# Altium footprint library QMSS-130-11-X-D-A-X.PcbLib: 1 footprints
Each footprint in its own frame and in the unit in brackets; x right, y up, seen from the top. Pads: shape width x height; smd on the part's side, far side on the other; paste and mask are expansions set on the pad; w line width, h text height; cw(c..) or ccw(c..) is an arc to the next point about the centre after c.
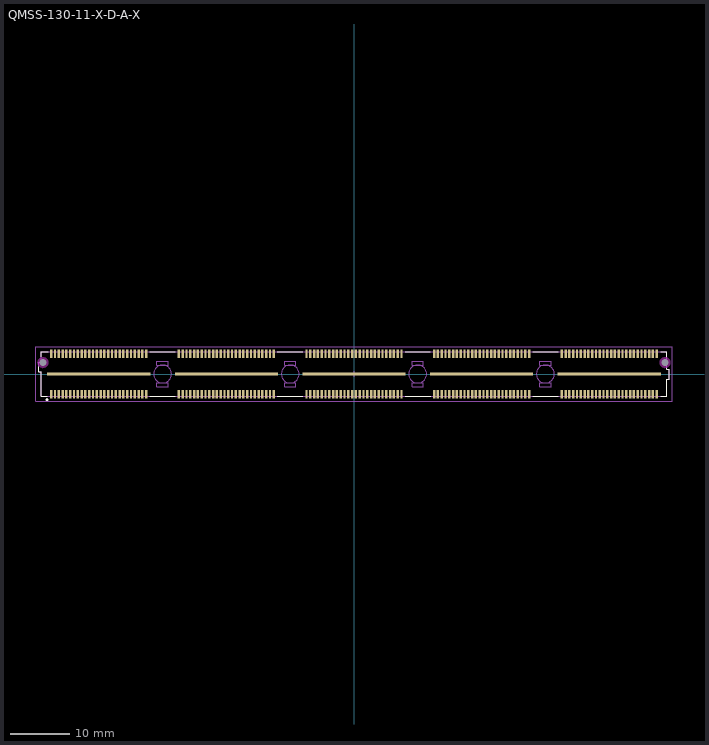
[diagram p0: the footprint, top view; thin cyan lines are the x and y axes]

## QMSS-130-11-X-D-A-X [mm] "0.635mm pitch, 260 pin, high speed shielded terminal; w/5 banks, w/40 signal pin/bank, w/12 GND pin/bank"
height 6.35
pads (267):
  rect 0.4x1.4 smd mask+0: 1(-50.62,-3.365) 2(-50.62,3.365) 3(-49.985,-3.365) 4(-49.985,3.365) 5(-49.35,-3.365) 6(-49.35,3.365) 7(-48.715,-3.365) 8(-48.715,3.365) 9(-48.08,-3.365) 10(-48.08,3.365) 11(-47.445,-3.365) 12(-47.445,3.365) 13(-46.81,-3.365) 14(-46.81,3.365) 15(-46.175,-3.365) 16(-46.175,3.365) 17(-45.54,-3.365) 18(-45.54,3.365) 19(-44.905,-3.365) 20(-44.905,3.365) 21(-44.27,-3.365) 22(-44.27,3.365) 23(-43.635,-3.365) 24(-43.635,3.365) 25(-43,-3.365) 26(-43,3.365) 27(-42.365,-3.365) 28(-42.365,3.365) 29(-41.73,-3.365) 30(-41.73,3.365) 31(-41.095,-3.365) 32(-41.095,3.365) 33(-40.46,-3.365) 34(-40.46,3.365) 35(-39.825,-3.365) 36(-39.825,3.365) 37(-39.19,-3.365) 38(-39.19,3.365) 39(-38.555,-3.365) 40(-38.555,3.365) 41(-37.92,-3.365) 42(-37.92,3.365) 43(-37.285,-3.365) 44(-37.285,3.365) 45(-36.65,-3.365) 46(-36.65,3.365) 47(-36.015,-3.365) 48(-36.015,3.365) 49(-35.38,-3.365) 50(-35.38,3.365) 51(-34.745,-3.365) 52(-34.745,3.365) 53(-13.405,3.365) 54(-13.405,-3.365) 55(-14.04,3.365) 56(-14.04,-3.365) 57(-14.675,-3.365) 58(-14.675,3.365) 59(-15.31,3.365) 60(-15.31,-3.365) 61(-15.945,3.365) 62(-15.945,-3.365) 63(-16.58,3.365) 64(-16.58,-3.365) 65(-17.215,-3.365) 66(-17.215,3.365) 67(-17.85,3.365) 68(-17.85,-3.365) 69(-18.485,3.365) 70(-18.485,-3.365) 71(-19.12,3.365) 72(-19.12,-3.365) 73(-19.755,-3.365) 74(-19.755,3.365) 75(-20.39,3.365) 76(-20.39,-3.365) 77(-21.025,3.365) 78(-21.025,-3.365) 79(-21.66,3.365) 80(-21.66,-3.365) 81(-22.295,3.365) 82(-22.295,-3.365) 83(-22.93,-3.365) 84(-22.93,3.365) 85(-23.565,-3.365) 86(-23.565,3.365) 87(-24.2,3.365) 88(-24.2,-3.365) 89(-24.835,-3.365) 90(-24.835,3.365) 91(-25.47,-3.365) 92(-25.47,3.365) 93(-26.105,3.365) 94(-26.105,-3.365) 95(-26.74,-3.365) 96(-26.74,3.365) 97(-27.375,-3.365) 98(-27.375,3.365) 99(-28.01,3.365) 100(-28.01,-3.365) 101(-28.645,-3.365) 102(-28.645,3.365) 103(-29.28,3.365) 104(-29.28,-3.365) 105(7.935,3.365) 106(7.935,-3.365) 107(7.3,3.365) 108(7.3,-3.365) 109(6.665,-3.365) 110(6.665,3.365) 111(6.03,3.365) 112(6.03,-3.365) 113(5.395,3.365) 114(5.395,-3.365) 115(4.76,3.365) 116(4.76,-3.365) 117(4.125,-3.365) 118(4.125,3.365) 119(3.49,3.365) 120(3.49,-3.365) 121(2.855,3.365) 122(2.855,-3.365) 123(2.22,3.365) 124(2.22,-3.365) 125(1.585,-3.365) 126(1.585,3.365) 127(0.95,3.365) 128(0.95,-3.365) 129(0.315,3.365) 130(0.315,-3.365) 131(-0.32,3.365) 132(-0.32,-3.365) 133(-0.955,3.365) 134(-0.955,-3.365) 135(-1.59,-3.365) 136(-1.59,3.365) 137(-2.225,-3.365) 138(-2.225,3.365) 139(-2.86,3.365) 140(-2.86,-3.365) 141(-3.495,-3.365) 142(-3.495,3.365) 143(-4.13,-3.365) 144(-4.13,3.365) 145(-4.765,3.365) 146(-4.765,-3.365) 147(-5.4,-3.365) 148(-5.4,3.365) 149(-6.035,-3.365) 150(-6.035,3.365) 151(-6.67,3.365) 152(-6.67,-3.365) 153(-7.305,-3.365) 154(-7.305,3.365) 155(-7.94,3.365) 156(-7.94,-3.365) 157(29.275,3.365) 158(29.275,-3.365) 159(28.64,3.365) 160(28.64,-3.365) 161(28.005,-3.365) 162(28.005,3.365) 163(27.37,3.365) 164(27.37,-3.365) 165(26.735,3.365) 166(26.735,-3.365) 167(26.1,3.365) 168(26.1,-3.365) 169(25.465,-3.365) 170(25.465,3.365) 171(24.83,3.365) 172(24.83,-3.365) 173(24.195,3.365) 174(24.195,-3.365) 175(23.56,3.365) 176(23.56,-3.365) 177(22.925,-3.365) 178(22.925,3.365) 179(22.29,3.365) 180(22.29,-3.365) 181(21.655,3.365) 182(21.655,-3.365) 183(21.02,3.365) 184(21.02,-3.365) 185(20.385,3.365) 186(20.385,-3.365) 187(19.75,-3.365) 188(19.75,3.365) 189(19.115,-3.365) 190(19.115,3.365) 191(18.48,3.365) 192(18.48,-3.365) 193(17.845,-3.365) 194(17.845,3.365) 195(17.21,-3.365) 196(17.21,3.365) 197(16.575,3.365) 198(16.575,-3.365) 199(15.94,-3.365) 200(15.94,3.365) 201(15.305,-3.365) 202(15.305,3.365) 203(14.67,3.365) 204(14.67,-3.365) 205(14.035,-3.365) 206(14.035,3.365) 207(13.4,3.365) 208(13.4,-3.365) 209(50.615,3.365) 210(50.615,-3.365) 211(49.98,3.365) 212(49.98,-3.365) 213(49.345,-3.365) 214(49.345,3.365) 215(48.71,3.365) 216(48.71,-3.365) 217(48.075,3.365) 218(48.075,-3.365) 219(47.44,3.365) 220(47.44,-3.365) 221(46.805,-3.365) 222(46.805,3.365) 223(46.17,3.365) 224(46.17,-3.365) 225(45.535,3.365) 226(45.535,-3.365) 227(44.9,3.365) 228(44.9,-3.365) 229(44.265,-3.365) 230(44.265,3.365) 231(43.63,3.365) 232(43.63,-3.365) 233(42.995,3.365) 234(42.995,-3.365) 235(42.36,3.365) 236(42.36,-3.365) 237(41.725,3.365) 238(41.725,-3.365) 239(41.09,-3.365) 240(41.09,3.365) 241(40.455,-3.365) 242(40.455,3.365) 243(39.82,3.365) 244(39.82,-3.365) 245(39.185,-3.365) 246(39.185,3.365) 247(38.55,-3.365) 248(38.55,3.365) 249(37.915,3.365) 250(37.915,-3.365) 251(37.28,-3.365) 252(37.28,3.365) 253(36.645,-3.365) 254(36.645,3.365) 255(36.01,3.365) 256(36.01,-3.365) 257(35.375,-3.365) 258(35.375,3.365) 259(34.74,3.365) 260(34.74,-3.365)
  rect 17.25x0.5 smd mask+0: 261(-42.68,0) 262(-21.34,0) 263(0,0) 264(21.34,0) 265(42.68,0)
  round 1 hole 1.2 unplated mask+0: 266(-52.015,1.91) 267(51.995,1.91)
Top Overlay:
  circle w0.25: c-51.35,-4.3 r0.125
  lines w0.2: -52.7,1.2 -52.7,0.35 -52.3,0.35 -52.3,-3.75 -51.25,-3.75 ; -52.3,2.85 -52.3,3.75 -51.15,3.75 ; -34.15,-3.75 -29.9,-3.75 ; -34.15,3.75 -29.9,3.75 ; -12.8,-3.75 -8.55,-3.75 ; -12.8,3.75 -8.55,3.75 ; 8.55,-3.75 12.8,-3.75 ; 8.55,3.75 12.75,3.75 ; 29.85,-3.75 34.15,-3.75 ; 29.85,3.75 34.15,3.75 ; 51.25,-3.75 52.3,-3.75 52.3,-0.85 52.7,-0.85 52.7,0.8 52.3,0.8 52.3,0.95 ; 51.25,3.75 52.3,3.75 52.3,2.85
Keep-Out Layer:
  pour cut-out: 52.903,1.91 52.872,2.145 52.781,2.364 52.637,2.552 52.449,2.696 52.23,2.787 51.995,2.818 51.76,2.787 51.541,2.696 51.353,2.552 51.209,2.364 51.118,2.145 51.087,1.91 51.118,1.675 51.209,1.456 51.353,1.268 51.541,1.124 51.76,1.033 51.995,1.002 52.23,1.033 52.449,1.124 52.637,1.268 52.781,1.456 52.872,1.675
  pour cut-out: -51.107,1.91 -51.138,2.145 -51.229,2.364 -51.373,2.552 -51.561,2.696 -51.78,2.787 -52.015,2.818 -52.25,2.787 -52.469,2.696 -52.657,2.552 -52.801,2.364 -52.892,2.145 -52.923,1.91 -52.892,1.675 -52.801,1.456 -52.657,1.268 -52.469,1.124 -52.25,1.033 -52.015,1.002 -51.78,1.033 -51.561,1.124 -51.373,1.268 -51.229,1.456 -51.138,1.675
Mechanical 12:
  lines w0.001: -52.7,0.35 -52.7,2 -52.3,2 -52.3,3.75 52.3,3.75 52.3,0.8 52.7,0.8 52.7,-0.85 52.3,-0.85 52.3,-3.75 -52.3,-3.75 -52.3,0.35 -52.7,0.35
Mechanical 13:
  circle w0.1: c-32,0 r1.5
  circle w0.1: c-10.65,0 r1.5
  circle w0.1: c10.65,0 r1.5
  circle w0.1: c32,0 r1.5
  lines w0.1: -52.7,0.35 -52.7,2 -52.3,2 -52.3,3.75 52.3,3.75 52.3,0.8 52.7,0.8 52.7,-0.85 52.3,-0.85 52.3,-3.75 -52.3,-3.75 -52.3,0.35 -52.7,0.35 ; -32.95,-2.15 -32.95,-1.5 -31.05,-1.5 -31.05,-2.15 -32.95,-2.15 ; -32.95,1.5 -32.95,2.15 -31.05,2.15 -31.05,1.5 -32.95,1.5 ; -11.6,-2.15 -11.6,-1.5 -9.7,-1.5 -9.7,-2.15 -11.6,-2.15 ; -11.6,1.5 -11.6,2.15 -9.7,2.15 -9.7,1.5 -11.6,1.5 ; 9.7,-2.15 9.7,-1.5 11.6,-1.5 11.6,-2.15 9.7,-2.15 ; 9.7,1.5 9.7,2.15 11.6,2.15 11.6,1.5 9.7,1.5 ; 31.05,-2.15 31.05,-1.5 32.95,-1.5 32.95,-2.15 31.05,-2.15 ; 31.05,1.5 31.05,2.15 32.95,2.15 32.95,1.5 31.05,1.5
  text ".Designator" at 0,0 h1.52
Mechanical 15:
  lines w0.05: -0.5,0 0.5,0 ; 0,-0.5 0,0.5 ; -53.2,-4.55 -53.2,4.55 53.2,4.55 53.2,-4.55 -53.2,-4.55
